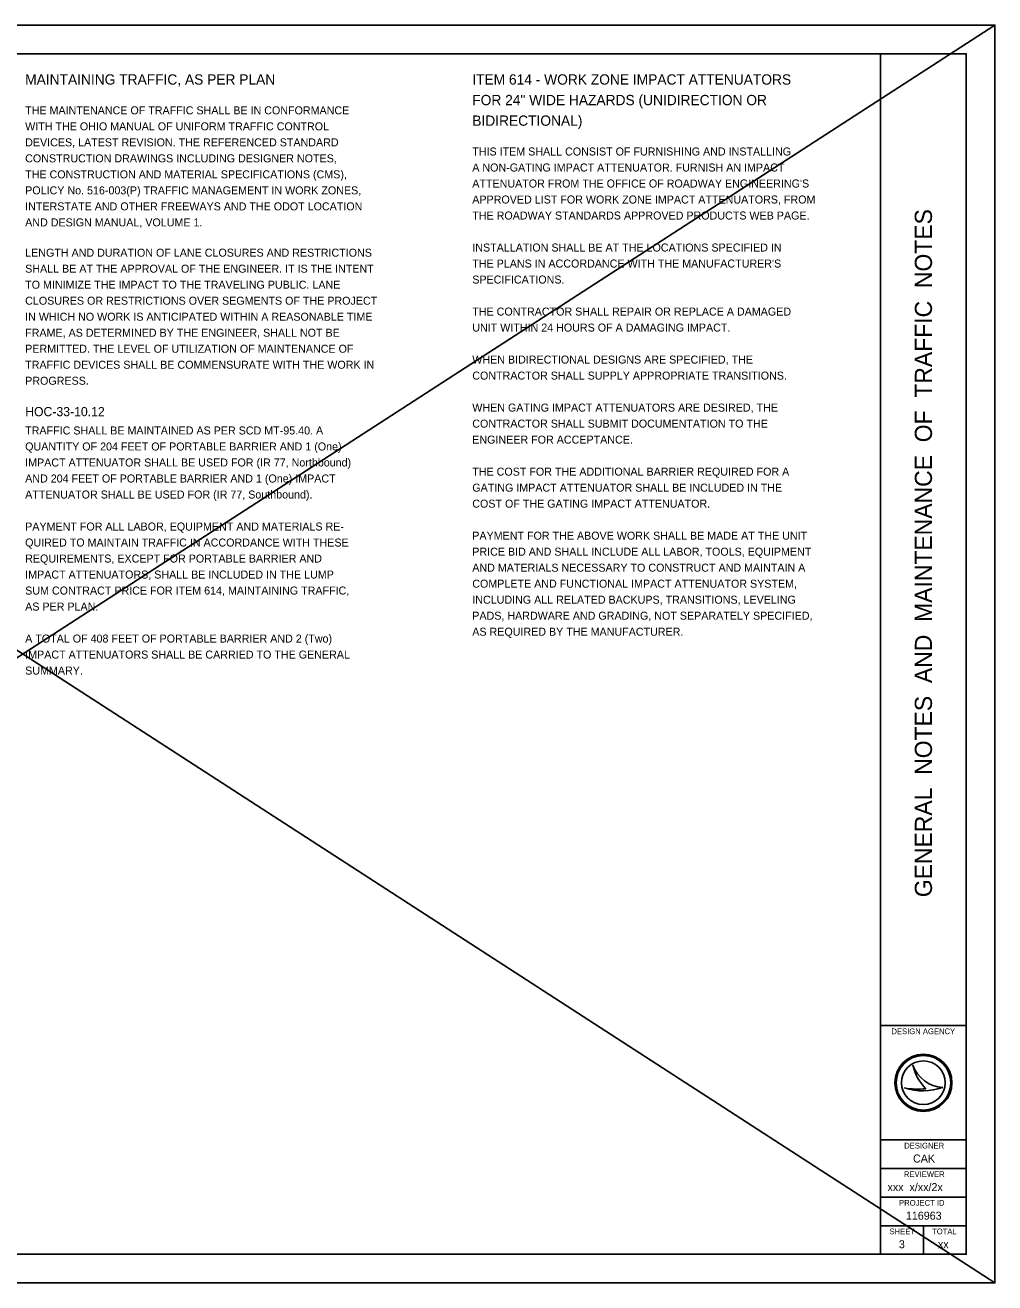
# Model space of a CAD drawing. Extents: x -37 to 104, y -26 to 49.
# Drawn here: x -19.66 to -2.7, y -1.68 to 20.32 of the extents above; entities that cross this region are included whole.
import ezdxf

# ---------------------------------------------------------------- set-up
doc = ezdxf.new("R2010")
doc.units = 0
for name, color, linetype in [('SH_Border', 7, 'Continuous'), ('SH_Cut_Line', 7, 'Continuous'), ('SH_Data', 7, 'Continuous'), ('SH_Text', 7, 'Continuous')]:
    doc.layers.add(name, color=color, linetype=linetype)

msp = doc.modelspace()

# ---------------------------------------------------------------- linework, layer by layer
at = {"layer": 'SH_Border'}
for p, q in [((-4.697, -1.18), (-4.697, 19.82)), ((-4.697, 2.82), (-3.197, 2.82)), ((-4.697, 0.82), (-3.197, 0.82)), ((-4.697, 0.32), (-3.197, 0.32)), ((-4.697, -0.18), (-3.197, -0.18)), ((-4.697, -0.68), (-3.197, -0.68))]:
    msp.add_line(p, q, dxfattribs=at)
msp.add_lwpolyline([(-35.197, 19.82), (-3.197, 19.82), (-3.197, -1.18), (-35.197, -1.18)], close=True, dxfattribs=at)
at = {"layer": 'SH_Cut_Line'}
msp.add_lwpolyline([(-36.697, -1.68), (-2.697, -1.68), (-2.697, 20.32), (-36.697, 20.32)], close=True, dxfattribs=at)
at = {"layer": 'SH_Data'}
for p, q in [((-4.13, 2.13), (-4.13, 2.13)), ((-3.947, 1.82), (-3.947, 1.82)), ((-4.28, 1.73), (-4.28, 1.73)), ((-3.61, 1.739), (-3.61, 1.739)), ((-3.947, -1.18), (-3.947, -0.68)), ((-4.322, -1.005), (-4.322, -1.005))]:
    msp.add_line(p, q, dxfattribs=at)
for radius in [0.5, 0.477, 0.477, 0.382]:
    msp.add_circle((-3.947, 1.82), radius, dxfattribs=at)
for centre, radius, start, end in [((-3.581, 2.318), 0.58, 198.9257, 198.9319), ((-3.351, 2.29), 0.796, 191.6379, 191.6421), ((-3.581, 2.318), 0.58, 198.9319, 267.1657), ((-3.351, 2.29), 0.796, 191.6421, 226.0947), ((-3.958, 2.69), 1.013, 251.4576, 290.0832), ((-4.049, 2.974), 1.266, 259.4964, 259.4995), ((-3.958, 2.69), 1.013, 251.4527, 251.4576), ((-4.049, 2.974), 1.266, 259.4995, 276.6672)]:
    msp.add_arc(centre, radius, start, end, dxfattribs=at)
at = {"layer": 'SH_Text'}
for p, q in [((-36.697, 20.32), (-2.697, -1.68)), ((-36.697, -1.68), (-2.697, 20.32))]:
    msp.add_line(p, q, dxfattribs=at)

# ---------------------------------------------------------------- texts
at = {"layer": 'SH_Data'}
msp.add_text('GENERAL  NOTES  AND  MAINTENANCE  OF  TRAFFIC  NOTES', height=0.3, rotation=90, dxfattribs=at).set_placement((-3.797, 5.066))
for s, height, p in [('DESIGN AGENCY', 0.1, (-4.506, 2.67)), ('DESIGNER', 0.1, (-4.283, 0.67)), ('CAK', 0.14, (-4.128, 0.425)), ('REVIEWER', 0.1, (-4.288, 0.17)), ('xxx  x/xx/2x', 0.14, (-4.575, -0.075)), ('PROJECT ID', 0.1, (-4.372, -0.33)), ('116963', 0.14, (-4.253, -0.575)), ('SHEET', 0.1, (-4.54, -0.83)), ('TOTAL', 0.1, (-3.795, -0.83)), ('3', 0.14, (-4.376, -1.075)), ('xx', 0.14, (-3.693, -1.075))]:
    msp.add_text(s, height=height, dxfattribs=at).set_placement(p)
at = {"layer": 'SH_Text'}
for s, height, p in [('MAINTAINING TRAFFIC, AS PER PLAN', 0.18, (-19.657, 19.28)), ('ITEM 614 - WORK ZONE IMPACT ATTENUATORS', 0.18, (-11.837, 19.28)), ('FOR 24" WIDE HAZARDS (UNIDIRECTION OR', 0.18, (-11.837, 18.92)), ('THE MAINTENANCE OF TRAFFIC SHALL BE IN CONFORMANCE', 0.14, (-19.657, 18.76)), ('BIDIRECTIONAL)', 0.18, (-11.837, 18.56)), ('WITH THE OHIO MANUAL OF UNIFORM TRAFFIC CONTROL', 0.14, (-19.657, 18.48)), ('DEVICES, LATEST REVISION. THE REFERENCED STANDARD', 0.14, (-19.657, 18.2)), ('CONSTRUCTION DRAWINGS INCLUDING DESIGNER NOTES,', 0.14, (-19.657, 17.92)), ('THIS ITEM SHALL CONSIST OF FURNISHING AND INSTALLING', 0.14, (-11.837, 18.04)), ('A NON-GATING IMPACT ATTENUATOR. FURNISH AN IMPACT', 0.14, (-11.837, 17.76)), ('THE CONSTRUCTION AND MATERIAL SPECIFICATIONS (CMS),', 0.14, (-19.657, 17.64)), ("ATTENUATOR FROM THE OFFICE OF ROADWAY ENGINEERING'S", 0.14, (-11.837, 17.48)), ('POLICY No. 516-003(P) TRAFFIC MANAGEMENT IN WORK ZONES,', 0.14, (-19.657, 17.36)), ('INTERSTATE AND OTHER FREEWAYS AND THE ODOT LOCATION', 0.14, (-19.657, 17.08)), ('APPROVED LIST FOR WORK ZONE IMPACT ATTENUATORS, FROM', 0.14, (-11.837, 17.2)), ('AND DESIGN MANUAL, VOLUME 1.', 0.14, (-19.657, 16.8)), ('THE ROADWAY STANDARDS APPROVED PRODUCTS WEB PAGE.', 0.14, (-11.837, 16.92)), ('INSTALLATION SHALL BE AT THE LOCATIONS SPECIFIED IN', 0.14, (-11.837, 16.36)), ('LENGTH AND DURATION OF LANE CLOSURES AND RESTRICTIONS', 0.14, (-19.657, 16.27)), ('SHALL BE AT THE APPROVAL OF THE ENGINEER. IT IS THE INTENT', 0.14, (-19.657, 15.99)), ("THE PLANS IN ACCORDANCE WITH THE MANUFACTURER'S", 0.14, (-11.837, 16.08)), ('TO MINIMIZE THE IMPACT TO THE TRAVELING PUBLIC. LANE', 0.14, (-19.657, 15.71)), ('SPECIFICATIONS.', 0.14, (-11.837, 15.8)), ('CLOSURES OR RESTRICTIONS OVER SEGMENTS OF THE PROJECT', 0.14, (-19.657, 15.43)), ('IN WHICH NO WORK IS ANTICIPATED WITHIN A REASONABLE TIME', 0.14, (-19.657, 15.15)), ('THE CONTRACTOR SHALL REPAIR OR REPLACE A DAMAGED', 0.14, (-11.837, 15.24)), ('FRAME, AS DETERMINED BY THE ENGINEER, SHALL NOT BE', 0.14, (-19.657, 14.87)), ('UNIT WITHIN 24 HOURS OF A DAMAGING IMPACT.', 0.14, (-11.837, 14.96)), ('PERMITTED. THE LEVEL OF UTILIZATION OF MAINTENANCE OF', 0.14, (-19.657, 14.59)), ('WHEN BIDIRECTIONAL DESIGNS ARE SPECIFIED, THE', 0.14, (-11.837, 14.4)), ('TRAFFIC DEVICES SHALL BE COMMENSURATE WITH THE WORK IN', 0.14, (-19.657, 14.31)), ('PROGRESS.', 0.14, (-19.657, 14.03)), ('CONTRACTOR SHALL SUPPLY APPROPRIATE TRANSITIONS.', 0.14, (-11.837, 14.12)), ('HOC-33-10.12', 0.16, (-19.657, 13.48)), ('WHEN GATING IMPACT ATTENUATORS ARE DESIRED, THE', 0.14, (-11.837, 13.56)), ('CONTRACTOR SHALL SUBMIT DOCUMENTATION TO THE', 0.14, (-11.837, 13.28)), ('TRAFFIC SHALL BE MAINTAINED AS PER SCD MT-95.40. A', 0.14, (-19.657, 13.16)), ('QUANTITY OF 204 FEET OF PORTABLE BARRIER AND 1 (One)', 0.14, (-19.657, 12.88)), ('ENGINEER FOR ACCEPTANCE.', 0.14, (-11.837, 13)), ('IMPACT ATTENUATOR SHALL BE USED FOR (IR 77, Northbound)', 0.14, (-19.657, 12.6)), ('THE COST FOR THE ADDITIONAL BARRIER REQUIRED FOR A', 0.14, (-11.837, 12.44)), ('AND 204 FEET OF PORTABLE BARRIER AND 1 (One) IMPACT', 0.14, (-19.657, 12.32)), ('ATTENUATOR SHALL BE USED FOR (IR 77, Southbound).', 0.14, (-19.657, 12.04)), ('GATING IMPACT ATTENUATOR SHALL BE INCLUDED IN THE', 0.14, (-11.837, 12.16)), ('COST OF THE GATING IMPACT ATTENUATOR.', 0.14, (-11.837, 11.88)), ('PAYMENT FOR ALL LABOR, EQUIPMENT AND MATERIALS RE-', 0.14, (-19.657, 11.48)), ('PAYMENT FOR THE ABOVE WORK SHALL BE MADE AT THE UNIT', 0.14, (-11.837, 11.32)), ('QUIRED TO MAINTAIN TRAFFIC IN ACCORDANCE WITH THESE', 0.14, (-19.657, 11.2)), ('REQUIREMENTS, EXCEPT FOR PORTABLE BARRIER AND', 0.14, (-19.657, 10.92)), ('PRICE BID AND SHALL INCLUDE ALL LABOR, TOOLS, EQUIPMENT', 0.14, (-11.837, 11.04)), ('IMPACT ATTENUATORS, SHALL BE INCLUDED IN THE LUMP', 0.14, (-19.657, 10.64)), ('AND MATERIALS NECESSARY TO CONSTRUCT AND MAINTAIN A', 0.14, (-11.837, 10.76)), ('COMPLETE AND FUNCTIONAL IMPACT ATTENUATOR SYSTEM,', 0.14, (-11.837, 10.48)), ('SUM CONTRACT PRICE FOR ITEM 614, MAINTAINING TRAFFIC,', 0.14, (-19.657, 10.36)), ('INCLUDING ALL RELATED BACKUPS, TRANSITIONS, LEVELING', 0.14, (-11.837, 10.2)), ('AS PER PLAN.', 0.14, (-19.657, 10.08)), ('PADS, HARDWARE AND GRADING, NOT SEPARATELY SPECIFIED,', 0.14, (-11.837, 9.92)), ('AS REQUIRED BY THE MANUFACTURER.', 0.14, (-11.837, 9.64)), ('A TOTAL OF 408 FEET OF PORTABLE BARRIER AND 2 (Two)', 0.14, (-19.657, 9.52)), ('IMPACT ATTENUATORS SHALL BE CARRIED TO THE GENERAL', 0.14, (-19.657, 9.24)), ('SUMMARY.', 0.14, (-19.657, 8.96))]:
    msp.add_text(s, height=height, dxfattribs=at).set_placement(p)

doc.saveas('drawing.dxf')
